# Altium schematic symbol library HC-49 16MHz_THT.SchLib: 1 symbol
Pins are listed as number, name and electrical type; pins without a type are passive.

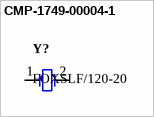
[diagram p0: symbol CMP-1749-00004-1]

## CMP-1749-00004-1
designator Y?, comment FOXSLF/120-20
Resistance Weld Thru-Hole Crystal, 12 MHz, +/-30 ppm, -20 to 70 degC, 2-Pin THD, RoHS, Bulk; Elements: 1; Rds On Max: 115 mohm; Typical Rise Time: 90 ns; Max Power Dissipation: 2.5 W; Case\Package: TO-251-3; Input Capacitance: 350 pF
footprint FOX-FOXSLF-2_V (THD, 2-Leads, Body 11.35x4.65mm, Pitch 4.88mm)
pins: 1, 2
